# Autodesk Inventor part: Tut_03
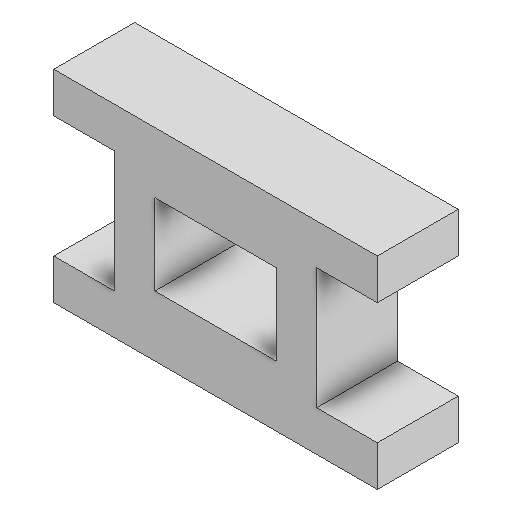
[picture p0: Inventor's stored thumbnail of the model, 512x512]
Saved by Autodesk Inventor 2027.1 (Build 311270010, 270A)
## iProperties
Created: 2022-07
Part Number: Tut_03
Material: Generic
Document SubType Name: Modeling
Designer: LENOVO-CADCIM
Density: 1 g/cm^3
Appearance: Default
Author: LENOVO-CADCIM
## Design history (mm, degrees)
sketch "Sketch1"
  geometry: L1 (0, 0)-(40, 0); L2 (40, 0)-(40, 10); L3 (40, 10)-(25, 10); L4 (25, 10)-(25, 40); L5 (25, 40)-(40, 40); L6 (40, 40)-(40, 50); L7 (40, 50)-(-40, 50); L8 (-40, 50)-(-40, 40); L9 (-40, 40)-(-25, 40); L10 (-25, 40)-(-25, 10); L11 (-25, 10)-(-40, 10); L12 (-40, 10)-(-40, 0); L13 (-40, 0)-(0, 0); L14 (-15, 15)-(15, 15); L15 (15, 15)-(15, 35); L16 (15, 35)-(-15, 35); L17 (-15, 35)-(-15, 15)
  constraints: 34 end point, 13 perpendicular, 2 horizontal, 2 parallel, 1 collinear, 1 point on line
  dimensions: "d0" = 40 distance of L1.start L1.end; "d1" = 10 distance of L1.end L2.end; "d2" = 15 distance of L2.end L3.end; "d3" = 30 distance between parallel lines of L3 L5; "d4" = 15 distance of L4.end L5.end; "d5" = 10 distance of L5.end L6.end; "d6" = 10 distance of L7.end L8.end; "d7" = 15 distance of L8.end L9.end; "d8" = 30 distance of L9.end L10.end; "d9" = 15 distance of L10.end L11.end; "d11" = 20 distance of L16.end L14.start; "d12" = 30 distance of L14.start L14.end; "d13" = 10 distance between parallel lines of L4 L15; "d14" = 15 distance between parallel lines of L14 L1
extrude "Extrusion1" new body sketch "Sketch1" distance "d15" = 20; taper "d16" = 0 deg
body "Solid1"
